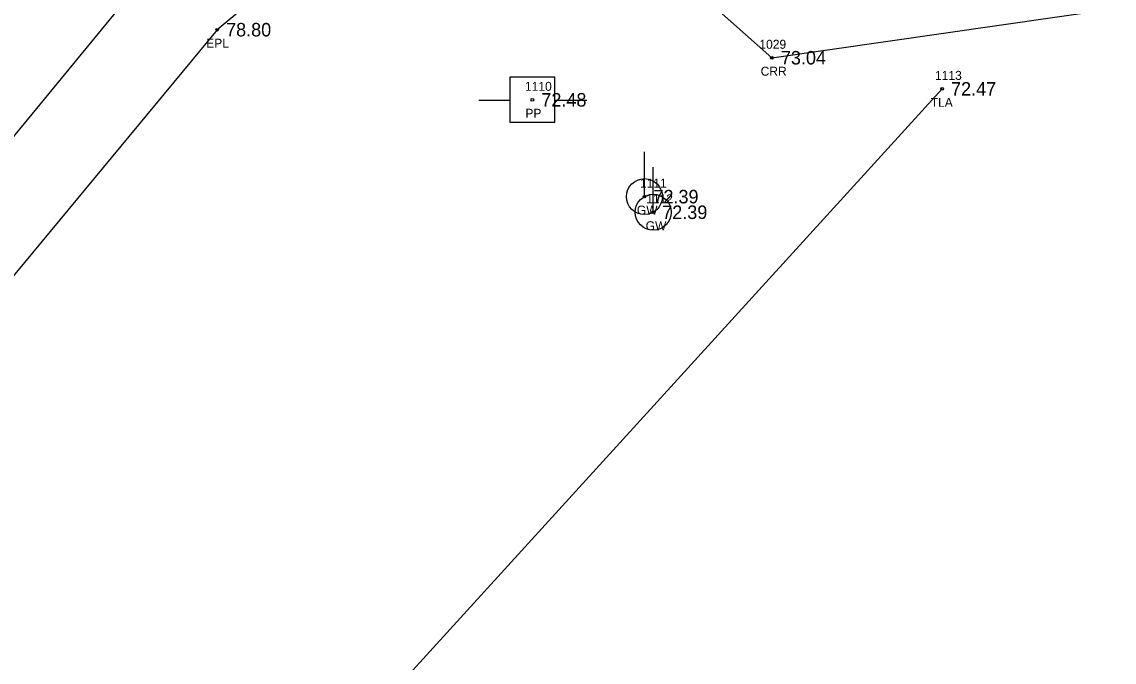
# Model space of a CAD drawing. Extents: x 2505249 to 2506333, y 912937 to 914171.
# Drawn here: x 2505748.6 to 2505870.1, y 913379.5 to 913450.7 of the extents above; entities that cross this region are included whole.
import ezdxf

# ---------------------------------------------------------------- set-up
doc = ezdxf.new("R2010")
doc.units = 0
for name, color, linetype in [('RD_EX_H2O', 7, 'Continuous'), ('RD_EX_H2O_txCode', 7, 'Continuous'), ('RD_EX_Road', 7, 'Continuous'), ('RD_EX_Road_txCode', 7, 'Continuous'), ('RD_EX_TX_H2O_ELEV', 7, 'Continuous'), ('RD_EX_TX_Road_ELEV', 7, 'Continuous'), ('RD_EX_TX_UT_ELEV', 7, 'Continuous'), ('RD_EX_TX_VEG_ELEV', 7, 'Continuous'), ('RD_EX_UT', 7, 'Continuous'), ('RD_EX_UT_txCode', 7, 'Continuous'), ('RD_EX_VEG', 7, 'Continuous'), ('RD_EX_VEG_txCode', 7, 'Continuous'), ('RD_HC_Cl', 7, 'Continuous'), ('RD_HC_Survey_ELEV', 7, 'Continuous'), ('RD_SMD_Locator', 7, 'Continuous')]:
    doc.layers.add(name, color=color, linetype=linetype)

msp = doc.modelspace()

# ---------------------------------------------------------------- linework, layer by layer
at = {"layer": 'RD_EX_H2O'}
msp.add_lwpolyline([(2505789.47, 913464.31), (2505795.69, 913463.1), (2505812.13, 913464.37), (2505832.03, 913446.73), (2505876.17, 913453.08), (2505891.76, 913474.03), (2505941.74, 913475.13), (2505995.42, 913465.05), (2506040.13, 913447.4), (2506076.3, 913432.47), (2506096.96, 913385.48)], dxfattribs=at)
at = {"layer": 'RD_EX_Road'}
msp.add_lwpolyline([(2505777.56, 913455.88), (2505770.31, 913449.85), (2505741, 913414.45), (2505705.55, 913374.27), (2505664.83, 913329.82), (2505624.02, 913288.23), (2505585.62, 913250.63), (2505516.95, 913183.5), (2505444.27, 913113.56), (2505370.6, 913041.78)], dxfattribs=at)
at = {"layer": 'RD_EX_UT'}
for p, q in [((2505807.88, 913444.56), (2505802.88, 913444.56)), ((2505802.88, 913444.56), (2505802.88, 913439.56)), ((2505807.88, 913439.56), (2505807.88, 913444.56)), ((2505799.44, 913442), (2505802.91, 913442)), ((2505807.8, 913442), (2505811.44, 913442)), ((2505802.88, 913439.56), (2505807.88, 913439.56)), ((2505817.85, 913431.28), (2505817.85, 913436.28)), ((2505818.83, 913429.54), (2505818.83, 913434.54))]:
    msp.add_line(p, q, dxfattribs=at)
for centre in [(2505817.85, 913431.28), (2505818.83, 913429.54)]:
    msp.add_circle(centre, 2, dxfattribs=at)
at = {"layer": 'RD_EX_VEG'}
msp.add_lwpolyline([(2505850.96, 913443.27), (2505787.55, 913373.63), (2505723.35, 913275.26), (2505541.65, 913152.37), (2505470.96, 913075.44), (2505402.9, 913005.93)], dxfattribs=at)
at = {"layer": 'RD_HC_Cl'}
msp.add_arc((2504276.95, 914656.3), 1909.83, 314.24205, 322.53164, dxfattribs=at)
at = {"layer": 'RD_SMD_Locator'}
for centre in [(2505770.31, 913449.85), (2505832.03, 913446.73), (2505850.96, 913443.27), (2505805.38, 913442.05), (2505817.85, 913431.28), (2505818.83, 913429.54)]:
    msp.add_circle(centre, 0.15, dxfattribs=at)

# ---------------------------------------------------------------- texts
at = {"layer": 'RD_EX_H2O_txCode'}
for s, p in [('1029', (2505830.64, 913447.73)), ('CRR', (2505830.78, 913444.73))]:
    msp.add_text(s, height=1, dxfattribs=at).set_placement(p)
at = {"layer": 'RD_EX_Road_txCode'}
msp.add_text('EPL', height=1, dxfattribs=at).set_placement((2505769.1, 913447.85))
at = {"layer": 'RD_EX_TX_H2O_ELEV'}
msp.add_text('73.04', height=1.5, dxfattribs=at).set_placement((2505833.03, 913445.98))
at = {"layer": 'RD_EX_TX_Road_ELEV'}
msp.add_text('78.80', height=1.5, dxfattribs=at).set_placement((2505771.31, 913449.1))
at = {"layer": 'RD_EX_TX_UT_ELEV'}
for p in [(2505818.85, 913430.53), (2505819.83, 913428.79)]:
    msp.add_text('72.39', height=1.5, dxfattribs=at).set_placement(p)
at = {"layer": 'RD_EX_TX_VEG_ELEV'}
msp.add_text('72.47', height=1.5, dxfattribs=at).set_placement((2505851.96, 913442.52))
at = {"layer": 'RD_EX_UT_txCode'}
for s, p in [('1110', (2505804.57, 913443.05)), ('PP', (2505804.61, 913440.05)), ('1111', (2505817.36, 913432.28)), ('1112', (2505818.05, 913430.54)), ('GW', (2505817.01, 913429.28)), ('GW', (2505817.99, 913427.54))]:
    msp.add_text(s, height=1, dxfattribs=at).set_placement(p)
at = {"layer": 'RD_EX_VEG_txCode'}
for s, p in [('1113', (2505850.18, 913444.27)), ('TLA', (2505849.7, 913441.27))]:
    msp.add_text(s, height=1, dxfattribs=at).set_placement(p)
at = {"layer": 'RD_HC_Survey_ELEV'}
msp.add_text('72.48', height=1.5, dxfattribs=at).set_placement((2505806.38, 913441.3))

doc.saveas('drawing.dxf')
